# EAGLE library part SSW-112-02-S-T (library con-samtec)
THROUGH-HOLE .025" SQ POST SOCKET Source: Samtec SSW.pdf
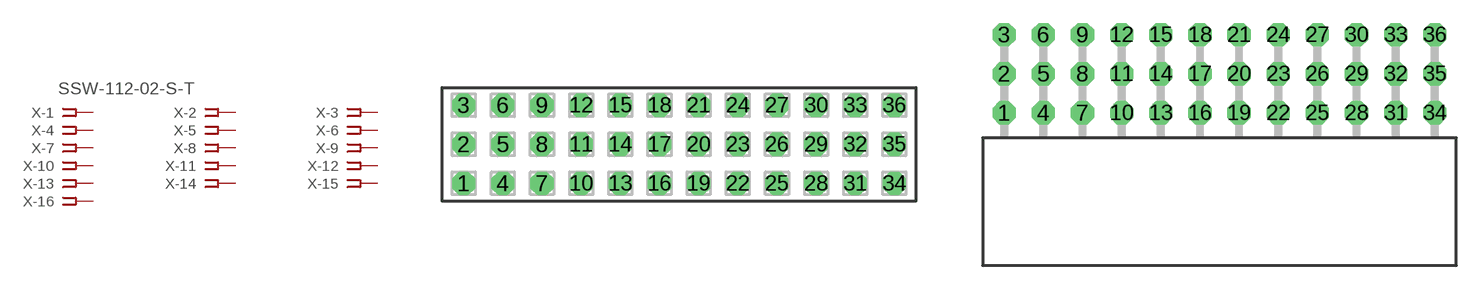
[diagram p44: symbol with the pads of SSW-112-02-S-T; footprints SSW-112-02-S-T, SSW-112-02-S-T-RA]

Designator prefix X; gates -1=FPINV -2=FPIN -3=FPIN -4=FPIN -5=FPIN -6=FPIN -7=FPIN -8=FPIN -9=FPIN -10=FPIN -11=FPIN -12=FPIN -13=FPIN -14=FPIN -15=FPIN -16=FPIN -17=FPIN -18=FPIN -19=FPIN -20=FPIN -21=FPIN -22=FPIN -23=FPIN -24=FPIN -25=FPIN -26=FPIN -27=FPIN -28=FPIN -29=FPIN -30=FPIN -31=FPIN -32=FPIN -33=FPIN -34=FPIN -35=FPIN -36=FPIN

## SSW-112-02-S-T (MPN: SSW-112-02-S-T; OC_FARNELL: unknown; OC_NEWARK: 82P5880)  [SSW-112-02-S-T]
1  -1:1  pas
2  -2:1  pas
3  -3:1  pas
4  -4:1  pas
5  -5:1  pas
6  -6:1  pas
7  -7:1  pas
8  -8:1  pas
9  -9:1  pas
10  -10:1  pas
11  -11:1  pas
12  -12:1  pas
13  -13:1  pas
14  -14:1  pas
15  -15:1  pas
16  -16:1  pas
17  -17:1  pas
18  -18:1  pas
19  -19:1  pas
20  -20:1  pas
21  -21:1  pas
22  -22:1  pas
23  -23:1  pas
24  -24:1  pas
25  -25:1  pas
26  -26:1  pas
27  -27:1  pas
28  -28:1  pas
29  -29:1  pas
30  -30:1  pas
31  -31:1  pas
32  -32:1  pas
33  -33:1  pas
34  -34:1  pas
35  -35:1  pas
36  -36:1  pas

## SSW-112-02-S-TRA (MPN: SSW-112-02-S-T-RA; OC_FARNELL: unknown; OC_NEWARK: 82P5881)  [SSW-112-02-S-T-RA]
Pads as for SSW-112-02-S-T

## Footprint SSW-112-02-S-T (pad centres in mm)
THROUGH-HOLE .025" SQ POST SOCKET Source: Samtec SSW.pdf
drill 1 pad 1.5 octagon: 1 -13.97,-2.54; 2 -13.97,0; 3 -13.97,2.54; 4 -11.43,-2.54; 5 -11.43,0; 6 -11.43,2.54; 7 -8.89,-2.54; 8 -8.89,0; 9 -8.89,2.54; 10 -6.35,-2.54; 11 -6.35,0; 12 -6.35,2.54; 13 -3.81,-2.54; 14 -3.81,0; 15 -3.81,2.54; 16 -1.27,-2.54; 17 -1.27,0; 18 -1.27,2.54; 19 1.27,-2.54; 20 1.27,0; 21 1.27,2.54; 22 3.81,-2.54; 23 3.81,0; 24 3.81,2.54; 25 6.35,-2.54; 26 6.35,0; 27 6.35,2.54; 28 8.89,-2.54; 29 8.89,0; 30 8.89,2.54; 31 11.43,-2.54; 32 11.43,0; 33 11.43,2.54; 34 13.97,-2.54; 35 13.97,0; 36 13.97,2.54

## Footprint SSW-112-02-S-T-RA (pad centres in mm)
THROUGH-HOLE .025" SQ POST SOCKET Source: Samtec SSW.pdf
drill 1 pad 1.5 octagon: 1 -13.97,1.524; 2 -13.97,4.064; 3 -13.97,6.604; 4 -11.43,1.524; 5 -11.43,4.064; 6 -11.43,6.604; 7 -8.89,1.524; 8 -8.89,4.064; 9 -8.89,6.604; 10 -6.35,1.524; 11 -6.35,4.064; 12 -6.35,6.604; 13 -3.81,1.524; 14 -3.81,4.064; 15 -3.81,6.604; 16 -1.27,1.524; 17 -1.27,4.064; 18 -1.27,6.604; 19 1.27,1.524; 20 1.27,4.064; 21 1.27,6.604; 22 3.81,1.524; 23 3.81,4.064; 24 3.81,6.604; 25 6.35,1.524; 26 6.35,4.064; 27 6.35,6.604; 28 8.89,1.524; 29 8.89,4.064; 30 8.89,6.604; 31 11.43,1.524; 32 11.43,4.064; 33 11.43,6.604; 34 13.97,1.524; 35 13.97,4.064; 36 13.97,6.604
